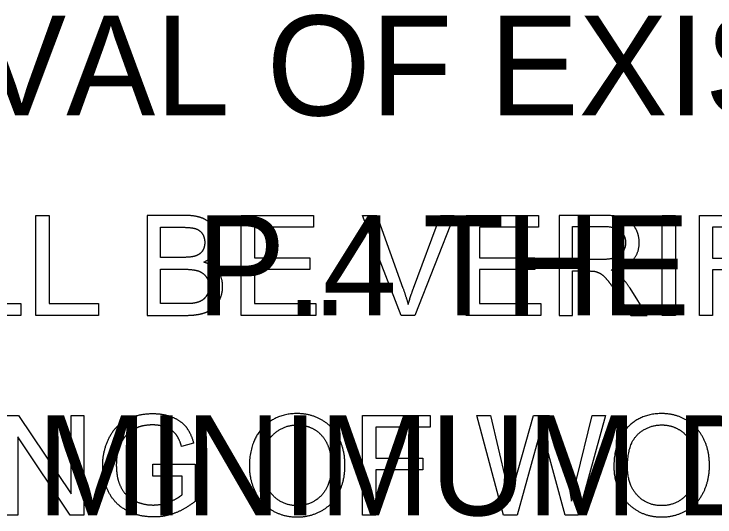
# Model space of a CAD drawing. Extents: x 12316 to 12541, y 1124 to 1850.
# Drawn here: x 12527.495 to 12528.477, y 1788.279 to 1788.983 of the extents above; entities that cross this region are included whole.
import ezdxf

# ---------------------------------------------------------------- set-up
doc = ezdxf.new("R2010")
doc.units = 0
doc.layers.add('SH_Text', color=7, linetype='Continuous')

msp = doc.modelspace()

# ---------------------------------------------------------------- linework, layer by layer
at = {"layer": 'SH_Text'}
for p, q in [((12527.7463, 1788.38201), (12527.72959, 1788.37743)), ((12527.82448, 1788.34937), (12527.82448, 1788.34937)), ((12527.84358, 1788.34913), (12527.84358, 1788.34913)), ((12528.33508, 1788.34937), (12528.33508, 1788.34937)), ((12528.35418, 1788.34913), (12528.35418, 1788.34913))]:
    msp.add_line(p, q, dxfattribs=at)
for points in [[(12527.41676, 1788.56117), (12527.41676, 1788.70117), (12527.43532, 1788.70117), (12527.43532, 1788.57771), (12527.50426, 1788.57771), (12527.50426, 1788.56117)], [(12527.52549, 1788.56117), (12527.52549, 1788.70117), (12527.54406, 1788.70117), (12527.54406, 1788.57771), (12527.61299, 1788.57771), (12527.61299, 1788.56117)], [(12527.81296, 1788.56117), (12527.81296, 1788.70117), (12527.91433, 1788.70117), (12527.91433, 1788.68463), (12527.83153, 1788.68463), (12527.83153, 1788.64184), (12527.9091, 1788.64184), (12527.9091, 1788.62531), (12527.83153, 1788.62531), (12527.83153, 1788.57771), (12527.91753, 1788.57771), (12527.91753, 1788.56117)], [(12528.12828, 1788.56117), (12528.12828, 1788.70117), (12528.22965, 1788.70117), (12528.22965, 1788.68463), (12528.14685, 1788.68463), (12528.14685, 1788.64184), (12528.22442, 1788.64184), (12528.22442, 1788.62531), (12528.14685, 1788.62531), (12528.14685, 1788.57771), (12528.23285, 1788.57771), (12528.23285, 1788.56117)], [(12528.40284, 1788.56117), (12528.40284, 1788.70117), (12528.4214, 1788.70117), (12528.4214, 1788.56117)], [(12528.45491, 1788.56117), (12528.45491, 1788.70117), (12528.54945, 1788.70117), (12528.54945, 1788.68463), (12528.47348, 1788.68463), (12528.47348, 1788.64131), (12528.53921, 1788.64131), (12528.53921, 1788.62477), (12528.47348, 1788.62477), (12528.47348, 1788.56117)], [(12527.48217, 1788.28117), (12527.48217, 1788.42117), (12527.50112, 1788.42117), (12527.57479, 1788.31122), (12527.57479, 1788.42117), (12527.5925, 1788.42117), (12527.5925, 1788.28117), (12527.57355, 1788.28117), (12527.49988, 1788.39113), (12527.49988, 1788.28117)], [(12527.98316, 1788.28117), (12527.98316, 1788.42117), (12528.0777, 1788.42117), (12528.0777, 1788.40463), (12528.00173, 1788.40463), (12528.00173, 1788.36131), (12528.06746, 1788.36131), (12528.06746, 1788.34477), (12528.00173, 1788.34477), (12528.00173, 1788.28117)]]:
    msp.add_lwpolyline(points, close=True, dxfattribs=at)
for points in [[(12527.7338, 1788.70117), (12527.68128, 1788.70117), (12527.68128, 1788.56117), (12527.73468, 1788.56117)], [(12528.05447, 1788.59951), (12528.09232, 1788.70117), (12528.11123, 1788.70117), (12528.05635, 1788.56117), (12528.03724, 1788.56117), (12527.98317, 1788.70117), (12528.00322, 1788.70117), (12528.03957, 1788.59951)], [(12528.32078, 1788.70117), (12528.25868, 1788.70117), (12528.25868, 1788.56117), (12528.27724, 1788.56117), (12528.27724, 1788.62338), (12528.29872, 1788.62338)], [(12528.31705, 1788.63939), (12528.27724, 1788.63939), (12528.27724, 1788.6857), (12528.32154, 1788.6857)], [(12527.73009, 1788.64238), (12527.69985, 1788.64238), (12527.69985, 1788.68463), (12527.7278, 1788.68463)], [(12527.73475, 1788.57771), (12527.69985, 1788.57771), (12527.69985, 1788.62584), (12527.73219, 1788.62584)], [(12528.34025, 1788.5903), (12528.35877, 1788.56117), (12528.38192, 1788.56117), (12528.35769, 1788.59928)], [(12528.22907, 1788.38787), (12528.19955, 1788.28117), (12528.18048, 1788.28117), (12528.14333, 1788.42117), (12528.16233, 1788.42117), (12528.18365, 1788.3294)], [(12528.19589, 1788.32664), (12528.22253, 1788.42117), (12528.24488, 1788.42117), (12528.26495, 1788.35032)], [(12528.28279, 1788.33122), (12528.30472, 1788.42117), (12528.32334, 1788.42117), (12528.28512, 1788.28117), (12528.26704, 1788.28117), (12528.23773, 1788.38788)], [(12527.73026, 1788.31004), (12527.73026, 1788.33602), (12527.68918, 1788.33602), (12527.68918, 1788.35256), (12527.7484, 1788.35256), (12527.7484, 1788.30067)]]:
    msp.add_lwpolyline(points, dxfattribs=at)
for points in [[(12527.75953, 1788.69692), (12527.74984, 1788.70117), (12527.7338, 1788.70117)], [(12527.77471, 1788.68384), (12527.76922, 1788.69267), (12527.75953, 1788.69692)], [(12528.34923, 1788.6974), (12528.33949, 1788.70117), (12528.32078, 1788.70117)], [(12528.36479, 1788.68408), (12528.35896, 1788.69363), (12528.34923, 1788.6974)], [(12528.32154, 1788.6857), (12528.3371, 1788.6857), (12528.34431, 1788.6793)], [(12527.7278, 1788.68463), (12527.74287, 1788.68463), (12527.74908, 1788.68268)], [(12527.74908, 1788.68268), (12527.75528, 1788.68072), (12527.75861, 1788.67543)], [(12527.7802, 1788.66536), (12527.7802, 1788.67501), (12527.77471, 1788.68384)], [(12528.34431, 1788.6793), (12528.35151, 1788.67291), (12528.35151, 1788.66298)], [(12528.37061, 1788.66298), (12528.37061, 1788.67453), (12528.36479, 1788.68408)], [(12527.75861, 1788.67543), (12527.76195, 1788.67014), (12527.76195, 1788.66317)], [(12527.76195, 1788.66317), (12527.76195, 1788.65583), (12527.75838, 1788.65096)], [(12527.77533, 1788.64845), (12527.7802, 1788.65638), (12527.7802, 1788.66536)], [(12528.35151, 1788.66298), (12528.35151, 1788.6562), (12528.34779, 1788.65042)], [(12528.36097, 1788.63786), (12528.37061, 1788.64808), (12528.37061, 1788.66298)], [(12527.75838, 1788.65096), (12527.7548, 1788.6461), (12527.74774, 1788.644)], [(12527.76062, 1788.63566), (12527.77046, 1788.64053), (12527.77533, 1788.64845)], [(12528.34779, 1788.65042), (12528.34407, 1788.64464), (12528.33691, 1788.64202)], [(12527.74774, 1788.644), (12527.7424, 1788.64238), (12527.73009, 1788.64238)], [(12528.33691, 1788.64202), (12528.32975, 1788.63939), (12528.31705, 1788.63939)], [(12528.33118, 1788.62488), (12528.35133, 1788.62765), (12528.36097, 1788.63786)], [(12527.78019, 1788.62296), (12527.77335, 1788.63193), (12527.76062, 1788.63566)], [(12527.73219, 1788.62584), (12527.74555, 1788.62584), (12527.75265, 1788.6235)], [(12527.75265, 1788.6235), (12527.75976, 1788.62116), (12527.76384, 1788.61538)], [(12527.78703, 1788.60176), (12527.78703, 1788.61398), (12527.78019, 1788.62296)], [(12528.29872, 1788.62338), (12528.30588, 1788.62338), (12528.30903, 1788.62271)], [(12528.30903, 1788.62271), (12528.31333, 1788.62166), (12528.31748, 1788.61897)], [(12528.31748, 1788.61897), (12528.32164, 1788.61628), (12528.32689, 1788.6096)], [(12528.34236, 1788.61791), (12528.33854, 1788.62135), (12528.33118, 1788.62488)], [(12528.35769, 1788.59928), (12528.35047, 1788.61046), (12528.34236, 1788.61791)], [(12527.76384, 1788.61538), (12527.76793, 1788.60961), (12527.76793, 1788.60178)], [(12528.32689, 1788.6096), (12528.33214, 1788.60291), (12528.34025, 1788.5903)], [(12527.76793, 1788.60178), (12527.76793, 1788.59509), (12527.76516, 1788.58998)], [(12527.78287, 1788.58347), (12527.78703, 1788.59192), (12527.78703, 1788.60176)], [(12528.03957, 1788.59951), (12528.04396, 1788.58729), (12528.04692, 1788.57659)], [(12528.04692, 1788.57659), (12528.05017, 1788.58805), (12528.05447, 1788.59951)], [(12527.76516, 1788.58998), (12527.76238, 1788.58487), (12527.75808, 1788.5822)], [(12527.74737, 1788.57838), (12527.74374, 1788.57771), (12527.73475, 1788.57771)], [(12527.75808, 1788.5822), (12527.75378, 1788.57953), (12527.74737, 1788.57838)], [(12527.77261, 1788.57044), (12527.77872, 1788.57502), (12527.78287, 1788.58347)], [(12527.75727, 1788.56351), (12527.76649, 1788.56585), (12527.77261, 1788.57044)], [(12527.73468, 1788.56117), (12527.74806, 1788.56117), (12527.75727, 1788.56351)], [(12527.65209, 1788.41503), (12527.66812, 1788.42363), (12527.68903, 1788.42363)], [(12527.68903, 1788.42363), (12527.70421, 1788.42363), (12527.71647, 1788.4187)], [(12527.89154, 1788.42363), (12527.86193, 1788.42363), (12527.84321, 1788.40392)], [(12527.9265, 1788.41437), (12527.91093, 1788.42363), (12527.89154, 1788.42363)], [(12528.40213, 1788.42363), (12528.37252, 1788.42363), (12528.3538, 1788.40392)], [(12528.43709, 1788.41437), (12528.42152, 1788.42363), (12528.40213, 1788.42363)], [(12527.62751, 1788.38872), (12527.63605, 1788.40644), (12527.65209, 1788.41503)], [(12527.71647, 1788.4187), (12527.72874, 1788.41377), (12527.73571, 1788.40497)], [(12527.95023, 1788.38855), (12527.94207, 1788.40511), (12527.9265, 1788.41437)], [(12528.46083, 1788.38855), (12528.45266, 1788.40511), (12528.43709, 1788.41437)], [(12527.66718, 1788.40386), (12527.65792, 1788.4), (12527.65224, 1788.3937)], [(12527.68913, 1788.40773), (12527.67643, 1788.40773), (12527.66718, 1788.40386)], [(12527.70841, 1788.40405), (12527.69972, 1788.40773), (12527.68913, 1788.40773)], [(12527.72177, 1788.39425), (12527.71709, 1788.40037), (12527.70841, 1788.40405)], [(12527.73571, 1788.40497), (12527.74267, 1788.39617), (12527.7463, 1788.38201)], [(12527.84321, 1788.40392), (12527.82448, 1788.38421), (12527.82448, 1788.34937)], [(12527.85777, 1788.39422), (12527.87196, 1788.40773), (12527.89163, 1788.40773)], [(12527.89163, 1788.40773), (12527.90549, 1788.40773), (12527.91661, 1788.40071)], [(12528.23323, 1788.40427), (12528.23093, 1788.39466), (12528.22907, 1788.38787)], [(12528.23773, 1788.38788), (12528.23395, 1788.40124), (12528.23323, 1788.40427)], [(12528.3538, 1788.40392), (12528.33508, 1788.38421), (12528.33508, 1788.34937)], [(12528.36836, 1788.39422), (12528.38255, 1788.40773), (12528.40223, 1788.40773)], [(12528.40223, 1788.40773), (12528.41608, 1788.40773), (12528.42721, 1788.40071)], [(12527.65224, 1788.3937), (12527.64656, 1788.3874), (12527.64341, 1788.37986)], [(12527.72959, 1788.37743), (12527.72645, 1788.38813), (12527.72177, 1788.39425)], [(12527.84358, 1788.34913), (12527.84358, 1788.38072), (12527.85777, 1788.39422)], [(12527.91661, 1788.40071), (12527.92774, 1788.3937), (12527.93352, 1788.38096)], [(12528.35418, 1788.34913), (12528.35418, 1788.38072), (12528.36836, 1788.39422)], [(12528.42721, 1788.40071), (12528.43834, 1788.3937), (12528.44412, 1788.38096)], [(12527.61897, 1788.35056), (12527.61897, 1788.371), (12527.62751, 1788.38872)], [(12527.9584, 1788.35099), (12527.9584, 1788.37199), (12527.95023, 1788.38855)], [(12528.469, 1788.35099), (12528.469, 1788.37199), (12528.46083, 1788.38855)], [(12527.64341, 1788.37986), (12527.63807, 1788.36688), (12527.63807, 1788.3517)], [(12527.93352, 1788.38096), (12527.9393, 1788.36822), (12527.9393, 1788.35113)], [(12528.44412, 1788.38096), (12528.4499, 1788.36822), (12528.4499, 1788.35113)], [(12527.62756, 1788.31321), (12527.61897, 1788.32993), (12527.61897, 1788.35056)], [(12527.63807, 1788.3517), (12527.63807, 1788.33299), (12527.64451, 1788.32039)], [(12527.82448, 1788.34937), (12527.82448, 1788.33094), (12527.83251, 1788.31443)], [(12527.8572, 1788.30928), (12527.84358, 1788.32384), (12527.84358, 1788.34913)], [(12527.9393, 1788.35113), (12527.9393, 1788.32412), (12527.92578, 1788.30942)], [(12527.94981, 1788.3129), (12527.9584, 1788.3297), (12527.9584, 1788.35099)], [(12528.26495, 1788.35032), (12528.27238, 1788.32393), (12528.2758, 1788.30075)], [(12528.33508, 1788.34937), (12528.33508, 1788.33094), (12528.3431, 1788.31443)], [(12528.36779, 1788.30928), (12528.35418, 1788.32384), (12528.35418, 1788.34913)], [(12528.4499, 1788.35113), (12528.4499, 1788.32412), (12528.43638, 1788.30942)], [(12528.4604, 1788.3129), (12528.469, 1788.3297), (12528.469, 1788.35099)], [(12528.18365, 1788.3294), (12528.18713, 1788.31499), (12528.18958, 1788.30075)], [(12528.18958, 1788.30075), (12528.19495, 1788.32319), (12528.19589, 1788.32664)], [(12528.2758, 1788.30075), (12528.27855, 1788.31402), (12528.28279, 1788.33122)], [(12527.653, 1788.28766), (12527.63615, 1788.2965), (12527.62756, 1788.31321)], [(12527.64451, 1788.32039), (12527.65095, 1788.3078), (12527.66326, 1788.30169)], [(12527.83251, 1788.31443), (12527.84053, 1788.29792), (12527.8561, 1788.28837)], [(12527.92545, 1788.28746), (12527.94121, 1788.2961), (12527.94981, 1788.3129)], [(12528.3431, 1788.31443), (12528.35113, 1788.29792), (12528.3667, 1788.28837)], [(12528.43604, 1788.28746), (12528.4518, 1788.2961), (12528.4604, 1788.3129)], [(12527.71289, 1788.30019), (12527.72434, 1788.30481), (12527.73026, 1788.31004)], [(12527.89135, 1788.29473), (12527.87081, 1788.29473), (12527.8572, 1788.30928)], [(12527.92578, 1788.30942), (12527.91227, 1788.29473), (12527.89135, 1788.29473)], [(12528.40194, 1788.29473), (12528.3814, 1788.29473), (12528.36779, 1788.30928)], [(12528.43638, 1788.30942), (12528.42286, 1788.29473), (12528.40194, 1788.29473)], [(12527.66326, 1788.30169), (12527.67557, 1788.29558), (12527.68941, 1788.29558)], [(12527.68941, 1788.29558), (12527.70144, 1788.29558), (12527.71289, 1788.30019)], [(12527.7484, 1788.30067), (12527.73475, 1788.2898), (12527.72024, 1788.28431)], [(12527.69046, 1788.27883), (12527.66984, 1788.27883), (12527.653, 1788.28766)], [(12527.72024, 1788.28431), (12527.70573, 1788.27883), (12527.69046, 1788.27883)], [(12527.8561, 1788.28837), (12527.87167, 1788.27883), (12527.89144, 1788.27883)], [(12527.89144, 1788.27883), (12527.90969, 1788.27883), (12527.92545, 1788.28746)], [(12528.3667, 1788.28837), (12528.38226, 1788.27883), (12528.40204, 1788.27883)], [(12528.40204, 1788.27883), (12528.42028, 1788.27883), (12528.43604, 1788.28746)]]:
    msp.add_open_spline(points, degree=2, dxfattribs=at)

# ---------------------------------------------------------------- texts
for s, p in [('THIS ITEM SHALL INCLUDE THE COMPLETE REMOVAL OF EXISTING ', (12522.87636, 1788.84117)), ('TREE(S) AS DETAILED ON TYPICAL DETAIL SHEET         .  THE ', (12522.87636, 1788.56117)), ('P.4', (12527.75035, 1788.56117)), ('REMOVAL SHALL INCLUDE STUMP REMOVAL TO A MINIMUM DEPTH ', (12522.87636, 1788.28117))]:
    msp.add_text(s, height=0.14, dxfattribs=at).set_placement(p)

doc.saveas('drawing.dxf')
